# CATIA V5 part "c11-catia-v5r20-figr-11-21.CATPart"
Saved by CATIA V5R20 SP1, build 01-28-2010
Part number: Part1
Bounding box of the stored display mesh (mm): x -89.703 to 75.958, y -127.286 to 108.862, z -26.487 to 19.815
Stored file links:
  D:\v5_r20\psrt_files_downloaded\c11\c11-catia-v5r20-figr-11-21.CATPart
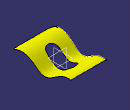
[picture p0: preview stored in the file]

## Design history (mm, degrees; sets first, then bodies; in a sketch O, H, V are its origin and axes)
Set1
  Extrude1: Element1 Sketch3, Lim1 86, Lim2 94, Direction yz-plane
  Sketch1 on xy-plane, origin (0, 0, 0), H (1, 0, 0), V (0, 1, 0)
    line L1 (64.3059, 108.8616) -> (75.9293, -106.0218)
    arc A1 centre (55.7837, -107.1115) radius 20.175 from (75.9293, -106.0218) to (55.7837, -127.2865) cw
    line L2 (55.7837, -127.2865) -> (-64.7868, -127.2865)
    arc A2 centre (-64.7868, -102.3613) radius 24.9252 from (-64.7868, -127.2865) to (-89.6873, -101.2501) cw
    line L3 (-89.6873, -101.2501) -> (-80.3115, 108.8616)
    line L4 (-80.3115, 108.8616) -> (64.3059, 108.8616)
    tangency: A1 L1, A2 L2, A2 L3, A1 L2
    horizontal: L2 H, L4 H
  Extrude2: Element1 Sketch1, Lim1 86, Lim2 94, Direction xy-plane
  Split1: ToCut Extrude1, Cutting Extrude2
  Sketch2 on xy-plane, origin (0, 0, 0), H (1, 0, 0), V (0, 1, 0)
    construction line L1 (-11.3849, 28.4134) -> (-11.3849, -36.9379)
    line L2 (12.8382, 28.4134) -> (12.8382, -36.9379)
    line L3 (-35.608, -36.9379) -> (-35.608, 28.4134)
    arc A1 centre (-11.3849, -36.9379) radius 24.2231 from (12.8382, -36.9379) to (-35.608, -36.9379) cw
    arc A2 centre (-11.3849, 28.4134) radius 24.2231 from (-35.608, 28.4134) to (12.8382, 28.4134) cw
    vertical: L1 V
    tangency: A1 L2, A2 L2, A1 L3, A2 L3
    parallelism: L1 L2
  Extrude3: Element1 Sketch2, Lim1 86, Lim2 94, Direction xy-plane
  Split2: ToCut Split1, Cutting Extrude3
  Boundary1: Boundary edge of Split2, Support Split2
Body1 (main body)
  Sketch3 on yz-plane, origin (0, 0, 0), H (0, 1, 0), V (0, 0, 1)
    spline S1 through (-130.9721, 0) (-85.5087, 19.8151) (-38.0512, 0) (0, -25.6483) (60.0541, -1.7202) (134.7951, -4.3868)
    point P1 (-130.9721, 0)
    point P2 (-38.0512, 0)
    point P3 (0, -25.6483)
    coincidence: P1 H, P2 H, P3 V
